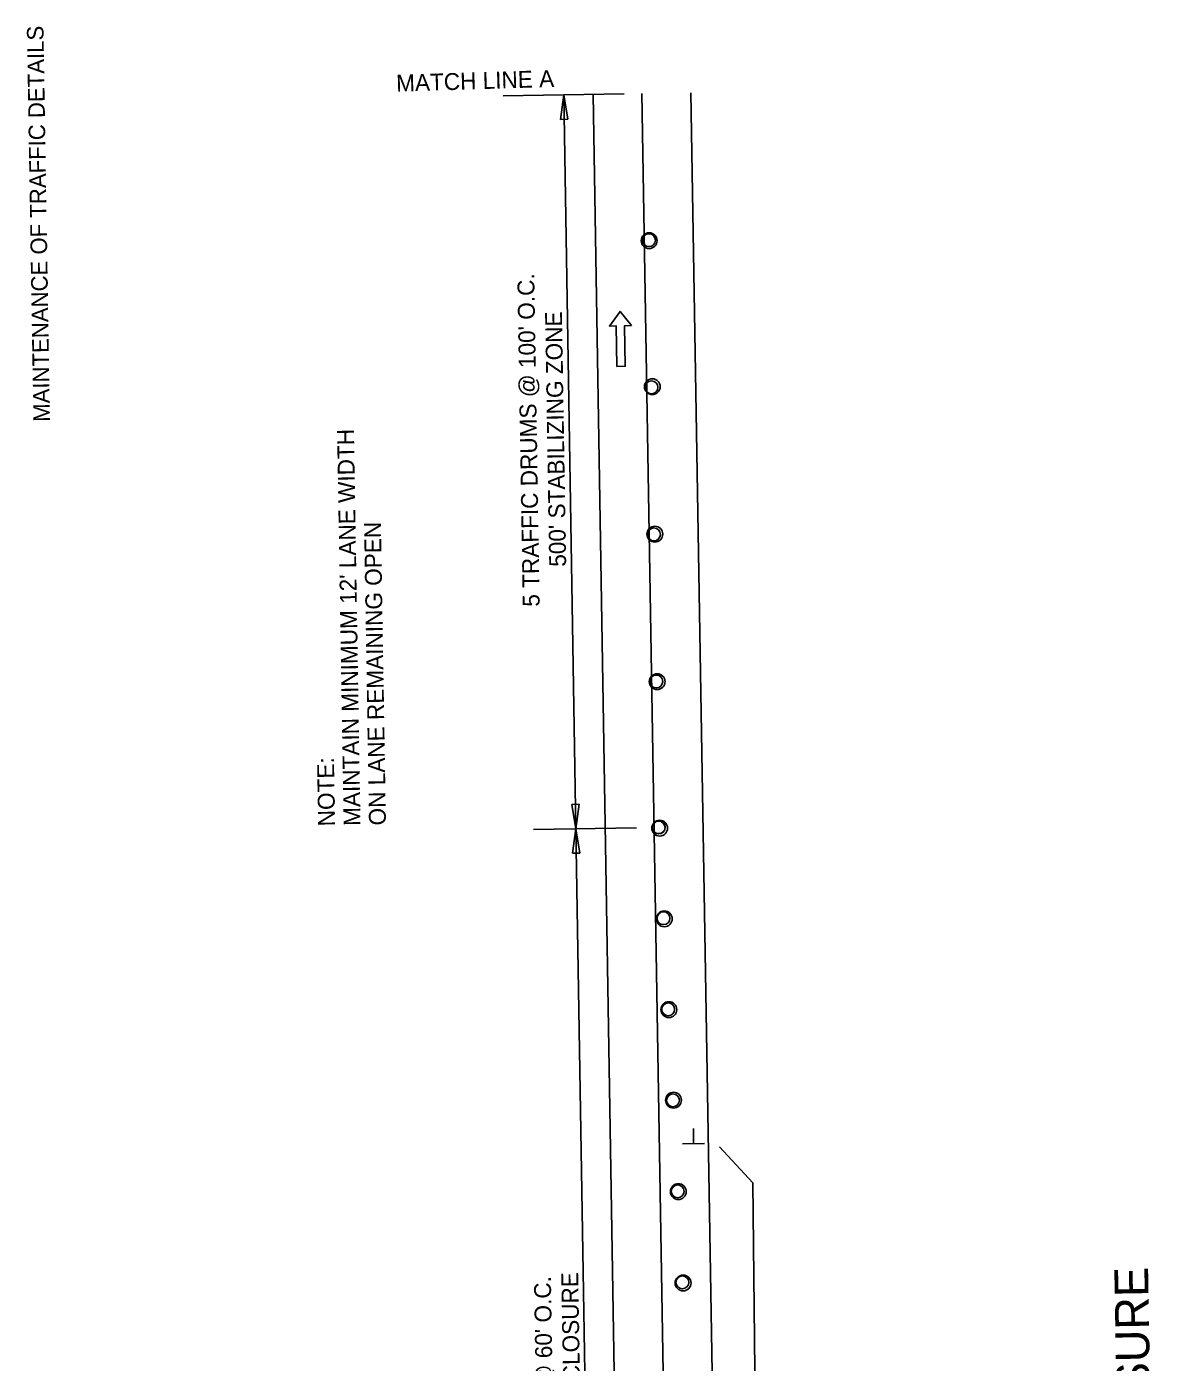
# Model space of a CAD drawing. Extents: x 1676639 to 1677883, y 226447 to 231777.
# Drawn here: x 1676896.1 to 1677305.5, y 229393.9 to 229877.9 of the extents above; entities that cross this region are included whole.
import ezdxf

# ---------------------------------------------------------------- set-up
doc = ezdxf.new("R2010")
doc.units = 0
for name, color, linetype in [('Default', 7, 'Continuous'), ('R_Annotation', 7, 'Continuous'), ('R_Border', 7, 'Continuous'), ('R_MOT', 7, 'Continuous')]:
    doc.layers.add(name, color=color, linetype=linetype)

msp = doc.modelspace()

# ---------------------------------------------------------------- linework, layer by layer
at = {"layer": 'Default'}
for p, q in [((1677068.79, 229852.81), (1677112.7, 229853.54)), ((1677089.57, 229844.29), (1677090.75, 229853.17)), ((1677090.75, 229853.17), (1677095.16, 229587.22)), ((1677090.75, 229853.17), (1677092.23, 229844.33)), ((1677113.41, 229126.42), (1677101.36, 229853.35)), ((1677131.14, 229126.72), (1677119.09, 229853.64)), ((1677148.87, 229127.01), (1677136.82, 229853.94)), ((1677092.23, 229844.33), (1677089.57, 229844.29)), ((1677093.68, 229596.07), (1677096.34, 229596.11)), ((1677095.16, 229587.22), (1677093.68, 229596.07)), ((1677096.34, 229596.11), (1677095.16, 229587.22)), ((1677079.82, 229586.97), (1677117.11, 229587.59)), ((1677093.97, 229578.34), (1677095.16, 229587.22)), ((1677095.16, 229587.22), (1677102.8, 229126.25)), ((1677095.16, 229587.22), (1677096.63, 229578.38)), ((1677096.63, 229578.38), (1677093.97, 229578.34)), ((1677137.82, 229473.22), (1677137.73, 229478.66)), ((1677141.79, 229473.17), (1677133.82, 229473.03))]:
    msp.add_line(p, q, dxfattribs=at)
msp.add_lwpolyline([(1677154.39, 229251.1), (1677161.14, 229263.02), (1677159.83, 229342.22), (1677168.16, 229343.05), (1677160.47, 229345.7), (1677159.29, 229458.95), (1677147.25, 229471.95)], dxfattribs=at)
for centre, radius in [((1677121.71, 229800.33), 2.87), ((1677121.67, 229800.51), 2.33), ((1677122.85, 229747.44), 2.87), ((1677122.55, 229747.2), 2.33), ((1677123.74, 229693.98), 2.87), ((1677123.44, 229693.89), 2.33), ((1677124.63, 229640.52), 2.87), ((1677124.32, 229640.59), 2.33), ((1677125.51, 229587.44), 2.87), ((1677125.17, 229587.66), 2.33), ((1677125.18, 229587.79), 2.33), ((1677127.19, 229554.56), 2.87), ((1677126.9, 229554.8), 2.33), ((1677128.86, 229521.69), 2.87), ((1677128.61, 229521.81), 2.33), ((1677130.53, 229488.86), 2.87), ((1677130.33, 229488.82), 2.33), ((1677132.27, 229455.74), 2.87), ((1677132.05, 229455.83), 2.33), ((1677134, 229422.61), 2.87), ((1677133.76, 229422.84), 2.33)]:
    msp.add_circle(centre, radius, dxfattribs=at)
at = {"layer": 'R_MOT'}
msp.add_lwpolyline([(1677115.27, 229769.55), (1677111.18, 229774.68), (1677107.27, 229769.41), (1677109.77, 229769.46), (1677110.02, 229754.75), (1677113.02, 229754.8), (1677112.77, 229769.51)], close=True, dxfattribs=at)

# ---------------------------------------------------------------- texts
at = {"layer": 'R_Annotation'}
for s, height, rotation, p in [('     MATCH LINE A', 6.1199, 1.7556, (1677018.72, 229853.97)), ("5 TRAFFIC DRUMS @ 100' O.C.", 6.1199, 90.9497, (1677082.03, 229667.74)), ("500' STABILIZING ZONE", 6.1199, 90.9497, (1677091.62, 229682.22)), ("MAINTAIN MINIMUM 12' LANE WIDTH", 6.1199, 90.9497, (1677017.08, 229588.31)), ('ON LANE REMAINING OPEN', 6.1199, 90.9497, (1677026.3, 229588.47)), ('NOTE:', 6.12, 90.9497, (1677007.85, 229588.16)), ("840' TAPER FOR LANE CLOSURE", 6.1199, 90.9497, (1677098.11, 229296.81)), ('RIGHT LANE CLOSURE', 12.2398, 90.9497, (1677305.55, 229246.67)), ("14 TRAFFIC DRUMS @ 60' O.C.", 6.1199, 90.9497, (1677088.06, 229304.35))]:
    msp.add_text(s, height=height, rotation=rotation, dxfattribs=at).set_placement(p)
at = {"layer": 'R_Border'}
msp.add_text('MAINTENANCE OF TRAFFIC DETAILS', height=6, rotation=90.9497, dxfattribs=at).set_placement((1676904.52, 229734.73))

doc.saveas('drawing.dxf')
